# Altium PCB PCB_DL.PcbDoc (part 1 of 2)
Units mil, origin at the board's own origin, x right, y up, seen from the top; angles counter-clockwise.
Board outline 3150 x 3254.21 mil, 2 copper layers (Top Layer, Bottom Layer); 110 components, 96 nets, 420 pads, 120 vias.
Unrouted connection lines stored in the file: 79.
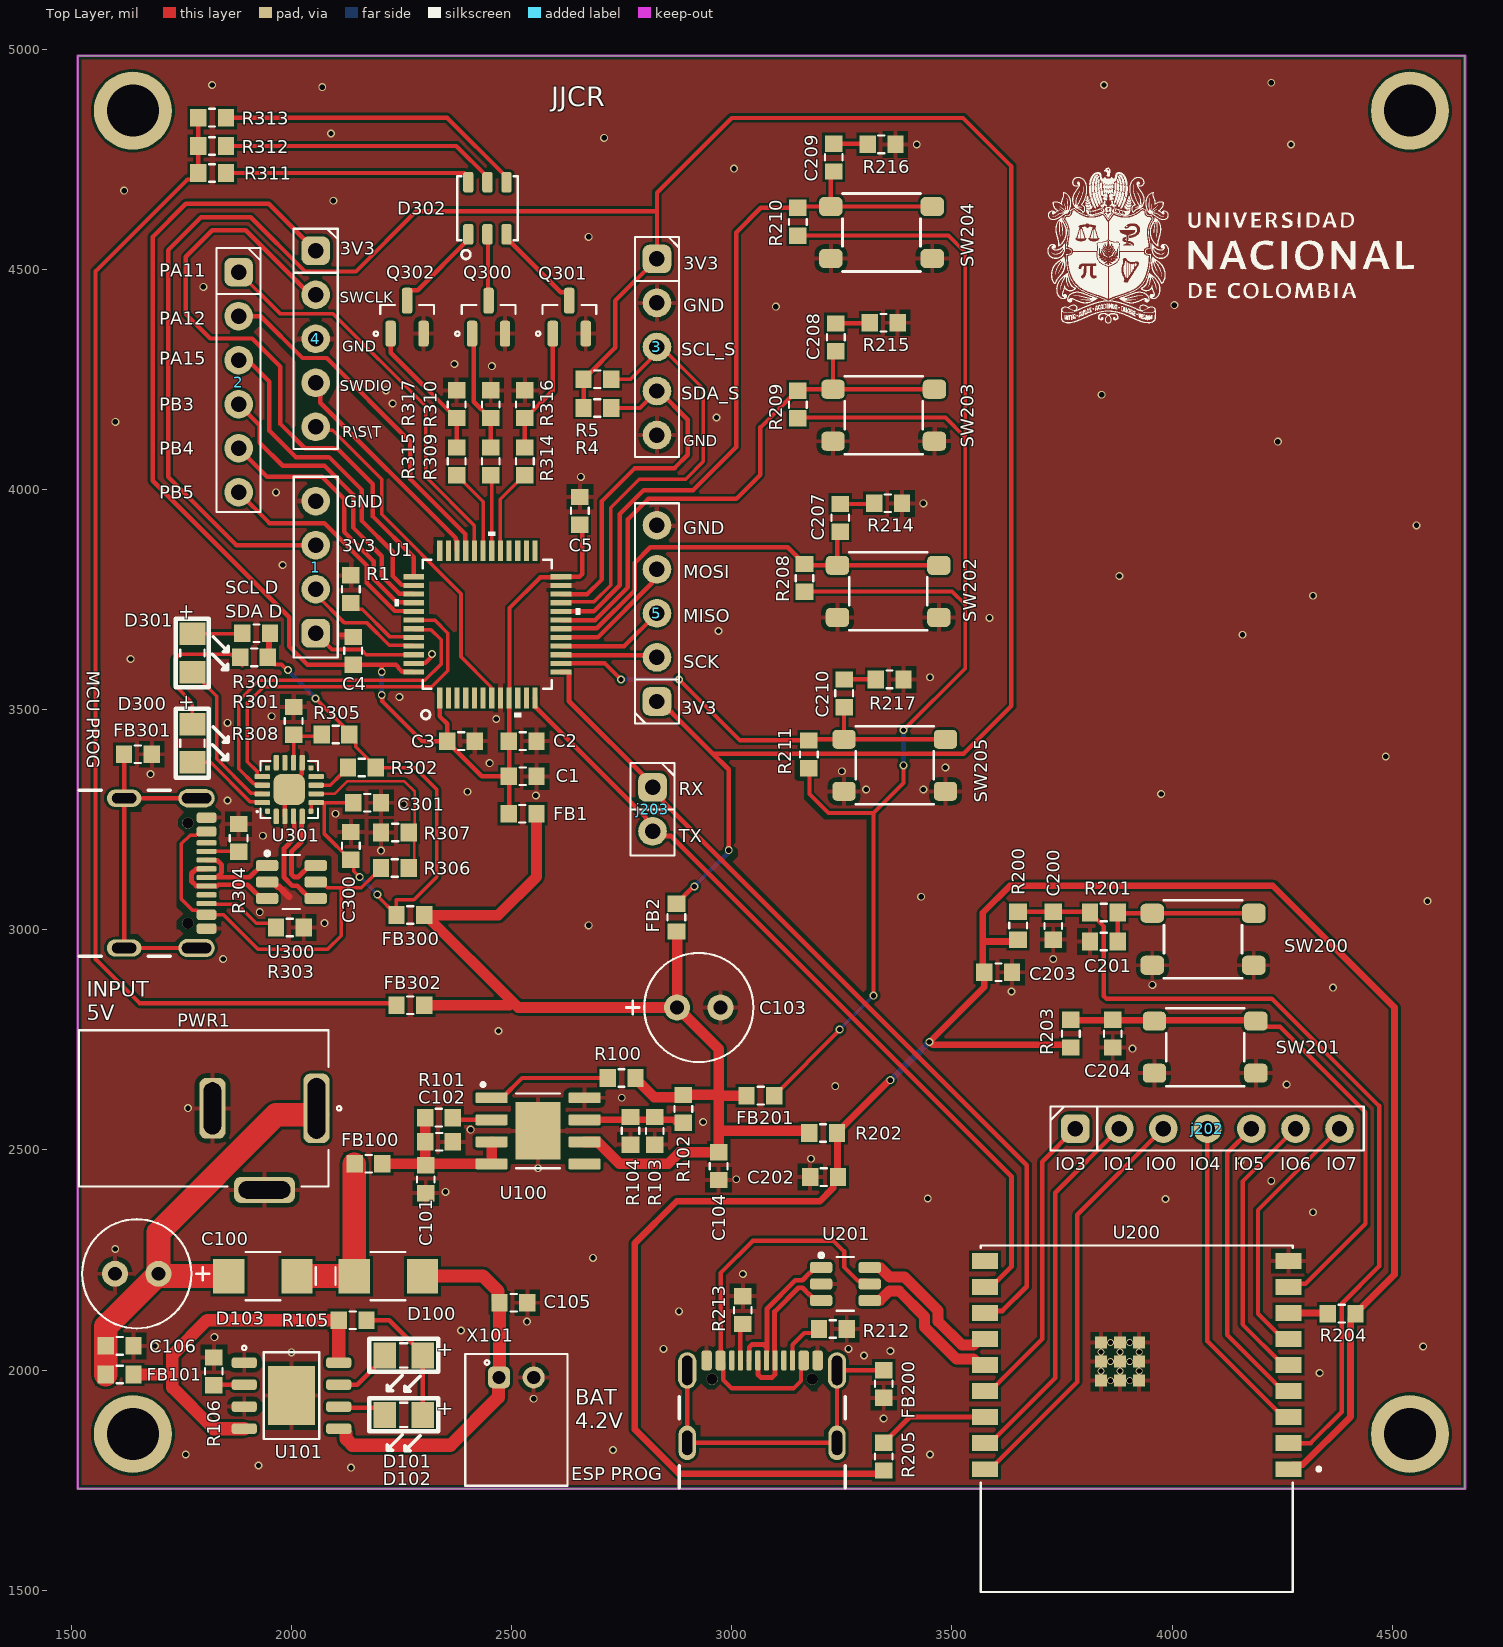
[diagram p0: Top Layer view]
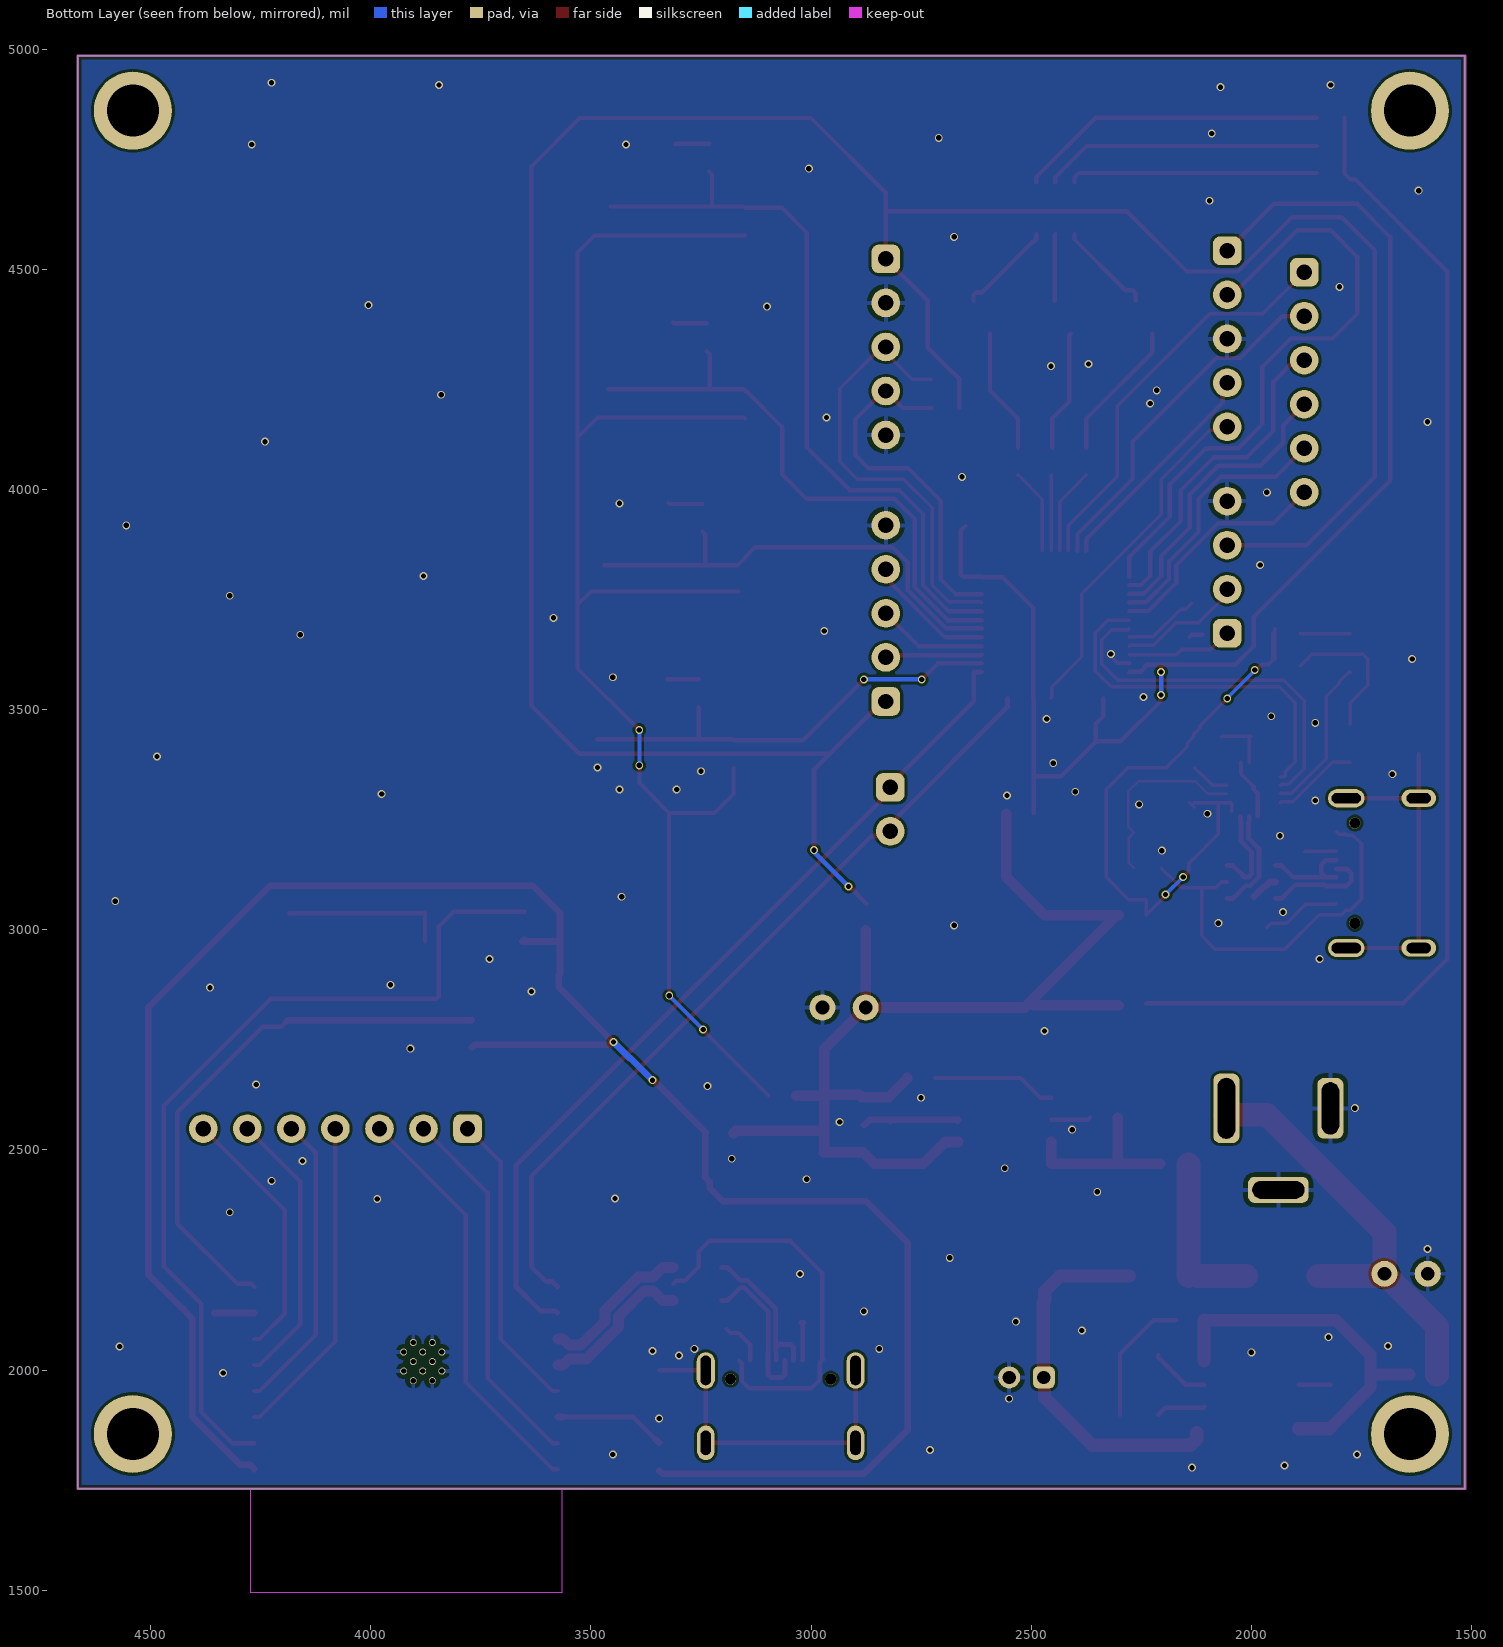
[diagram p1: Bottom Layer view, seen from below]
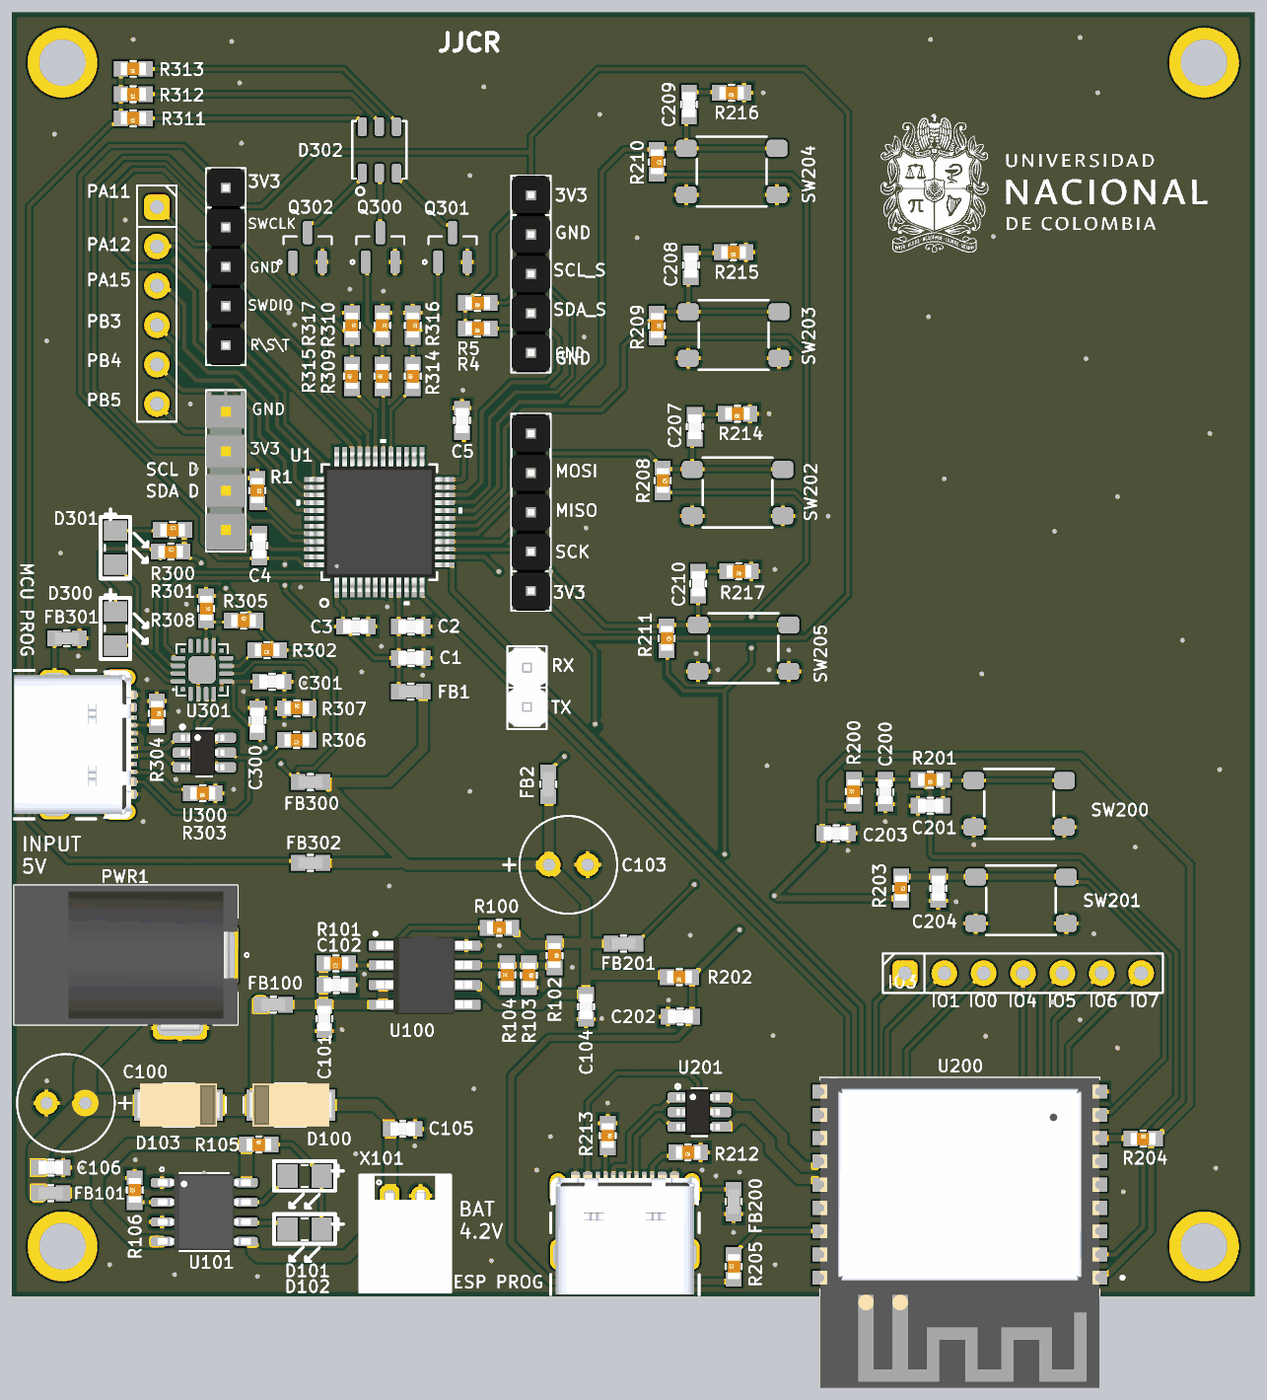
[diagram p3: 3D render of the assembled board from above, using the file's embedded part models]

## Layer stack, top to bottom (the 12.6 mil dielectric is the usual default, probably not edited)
Top Solder: solder mask 0.4, Solder Resist, Dk 3.5
Top Layer: signal copper 1.4
Dielectric 1: dielectric 12.6, FR-4, Dk 4.8
Bottom Layer: signal copper 1.4
Bottom Solder: solder mask 0.4, Solder Resist, Dk 3.5

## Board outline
1515,1730.39 4665,1730.39 4665,4984.61 1515,4984.61

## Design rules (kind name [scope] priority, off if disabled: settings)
Clearance [All] p1: gap=6 ignorepadtopadclearanceinfootprint=FALSE
DiffPairsRouting [InDifferentialPairClass('USB_2.0')] p1: maxlimit=6 minlimit=6 mostfreqgap=6 toplayer_minwidth=11 toplayer_maxwidth=31 toplayer_prefwidth=31 bottomlayer_minwidth=11 bottomlayer_maxwidth=31 bottomlayer_prefwidth=31 maxuncoupledlength=500
HoleSize [All] p1: absolutevalues=TRUE maxlimit=200 minlimit=12 maxpercent=80.000 minpercent=20.000
MatchedLengths [InDifferentialPairClass('USB_2.0')] p1: tolerance=50 checknetsindiffpair=TRUE checkdiffpairvsdiffpair=FALSE checkxsignals=FALSE checkothers=FALSE
MinimumSolderMaskSliver [All] p1: minsoldermaskwidth=4
PolygonConnect PolygonConnect_1 [IsVia] p1: connectstyle=Direct reliefconductorwidth=10 reliefentries=4 polygonreliefangle="90 Angle" airgapwidth=10
PolygonConnect [All] p2: connectstyle=Relief reliefconductorwidth=10 reliefentries=4 polygonreliefangle="90 Angle" airgapwidth=10
RoutingVias [All] p1: holewidth=12 width=18 viastyle="Through Hole" minholewidth=12 minwidth=18 maxholewidth=50 maxwidth=50
SilkToSilkClearance [All] p1: silktosilkclearance=0.1
SilkToSolderMaskClearance [IsPad] p1: minsilkscreentomaskgap=1 clearancetoexposedcopper=TRUE
SolderMaskExpansion [All] p1: expansion=4 istentingtop=FALSE
SupplyNets "Schematic Supply Nets_12" [InNet('3V3_BTN')] p1: voltage=0.000
SupplyNets "Schematic Supply Nets_11" [InNet('3V3_EXT')] p2: voltage=0.000
SupplyNets "Schematic Supply Nets_10" [InNet('3V3_LED')] p3: voltage=0.000
SupplyNets "Schematic Supply Nets_9" [InNet('VBUS2')] p4: voltage=0.000
SupplyNets "Schematic Supply Nets_8" [InNet('VBAT')] p5: voltage=0.000
SupplyNets "Schematic Supply Nets_7" [InNet('3V3')] p6: voltage=0.000
SupplyNets "Schematic Supply Nets_6" [InNet('VLDO')] p7: voltage=0.000
SupplyNets "Schematic Supply Nets_5" [InNet('3V3_CP')] p8: voltage=0.000
SupplyNets "Schematic Supply Nets_4" [InNet('GND')] p9: voltage=0.000
SupplyNets "Schematic Supply Nets_3" [InNet('5V')] p10: voltage=0.000
SupplyNets "Schematic Supply Nets_2" [InNet('3V3_MCU')] p11: voltage=0.000
SupplyNets "Schematic Supply Nets_1" [InNet('3V3_ESP')] p12: voltage=0.000
SupplyNets "Schematic Supply Nets" [InNet('VBUS')] p13: voltage=0.000
Width Width_2 [InNet('5V')] p1: maxlimit=54 minlimit=50 preferedwidth=54
Width Width_6 [InNet('VLDO')] p2: maxlimit=54 minlimit=50 preferedwidth=54
Width Width_4 [InNet('3V3_ESP')] p3: maxlimit=15 minlimit=10 preferedwidth=15
Width [InNet('3V3')] p4: maxlimit=24 minlimit=24 preferedwidth=24
Width Width_7 [InNet('VBAT')] p5: maxlimit=30 minlimit=30 preferedwidth=30
Width Width_3 [InNet('3V3_MCU')] p6: maxlimit=10 minlimit=8 preferedwidth=10
Width Width_5 [InNet('3V3_CP')] p7: maxlimit=10 minlimit=8 preferedwidth=10
Width Width_1 [All] p8: maxlimit=100 minlimit=6 preferedwidth=10
25 further rules are at their usual default settings.

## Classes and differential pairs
component class POWER: C100 C101 C102 C103 C104 C105 C106 D100 D101 D102 D103 FB100 FB101 PWR1 R100 R101 R102 R103 R104 R105 R106 U100 U101 X101
component class MCU: 1 2 3 4 5 C1 C2 C3 C4 C5 FB1 FB2 R1 R4 R5 U1
component class CP2102: C300 C301 D300 D301 D302 FB300 FB301 FB302 "MCU PROG" Q300 Q301 Q302 R300 R301 R302 R303 R304 R305 R306 R307 R308 R309 R310 R311 R312 R313 R314 R315 R316 R317 U300 U301
differential pair class USB_2.0: D2_C D_C DATA DATA_ESP DATA_MCU
component class ESP: C200 C201 C202 C203 C204 C207 C208 C209 C210 "ESP PROG" FB200 FB201 j200 j202 j203 R200 R201 R202 R203 R204 R205 R208 R209 R210 R211 R212 R213 R214 R215 R216 R217 SW200 SW201 SW202 SW203 SW204 SW205 U200 U201
differential pair D2_C: +D2_C_P -D2_C_N
differential pair DATA_MCU: +DATA_MCU_P -DATA_MCU_N
differential pair DATA_ESP: +DATA_ESP_P -DATA_ESP_N
differential pair D_C: +D_C_P -D_C_N

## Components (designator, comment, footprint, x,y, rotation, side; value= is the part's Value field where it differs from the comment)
1 "4x1" H_4x1_TH_2.54mm 2055.07,3823.5 r90 top
2 "6x1" H_6x1_TH_100mil 1880.07,4243.5 r270 top
3 "5x1" H_5x1_TH_100mil 2830.07,4323.5 r270 top
4 "5x1" H_5x1_TH_100mil 2055,4342 r270 top
5 "5x1" H_5x1_TH_100mil 2830.07,3718.5 r90 top
C1 "10uF 10V" 0603_cap 2525.07,3348.5 r0 top value=10uF
C2 "0.1uF 50V" 0603_cap 2525.07,3428.5 r0 top value=0.1uF
C3 "0.1uF 50V" 0603_cap 2385.07,3428.5 r0 top value=0.1uF
C4 "0.1uF 50V" 0603_cap 2140.07,3633.5 r90 top value=0.1uF
C5 "0.1uF 50V" 0603_cap 2655.07,3951.5 r90 top value=0.1uF
C100 "100uF 35V" CAP_TH_2.5MM_6.3*12MM 1648.75,2218.82 r180 top value=100uF
C101 "10uF 10V" 0603_cap 2305.07,2433.5 r270 top value=10uF
C102 "1uF 50V" 0603_cap 2335.07,2518.5 r0 top value=1uF
C103 "100uF 35V" CAP_TH_2.5MM_6.3*12MM 2925.07,2823.5 r0 top value=100uF
C104 "10uF 10V" 0603_cap 2970.07,2463.5 r270 top value=10uF
C105 "10uF 10V" 0603_cap 2504.18,2153.02 r0 top value=10uF
C106 "10uF 10V" 0603_cap 1610,2055 r0 top value=10uF
C200 "0.1uF 50V" 0603_cap 3730.07,3009.21 r270 top value=0.1uF
C201 "0.1uF 50V" 0603_cap 3845.07,2973.5 r180 top value=0.1uF
C202 "10uF 10V" 0603_cap 3209.57,2438.5 r180 top value=10uF
C203 "0.1uF 50V" 0603_cap 3605.07,2903.5 r0 top value=0.1uF
C204 "0.1uF 50V" 0603_cap 3865.07,2764.21 r270 top value=0.1uF
C207 "0.1uF 50V" 0603_cap 3246.49,3935.5 r90 top value=0.1uF
C208 "0.1uF 50V" 0603_cap 3236.49,4345.5 r90 top value=0.1uF
C209 "0.1uF 50V" 0603_cap 3231.49,4753.5 r90 top value=0.1uF
C210 "0.1uF 50V" 0603_cap 3255.07,3537 r90 top value=0.1uF
C300 "10uF 10V" 0603_cap 2135.07,3190.5 r90 top value=10uF
C301 "0.1uF 50V" 0603_cap 2172.07,3288.5 r0 top value=0.1uF
D100 "30V 3A" SMA 2220.07,2213.5 r0 top
D101 "2.9V" 0805_LED 2255.07,1898.5 r180 top
D102 "2V" 0805_LED 2255.07,2033.5 r180 top
D103 "30V 3A" SMA 1935.07,2213.5 r180 top
D300 "2V" 0805_LED 1775.07,3423.5 r270 top
D301 "2.9V" 0805_LED 1775.07,3628.5 r270 top
D302 "RGB" RGB_NS_3.5X3.7 2445.07,4638.5 r90 top
"ESP PROG" "USB C" CON_USB_C_16P_RA#1 3068.93,1928.38 r0 top
FB1 "60OHM 2A" 0603_fb 2525.07,3263.5 r180 top value="60 OHM"
FB2 "60OHM 2A" 0603_fb 2874.36,3027.75 r90 top value="60 OHM"
FB100 "60OHM 2A" 0603_fb 2175.07,2468.5 r0 top value="60 OHM"
FB101 "60OHM 2A" 0603_fb 1610,1990.17 r0 top value="60 OHM"
FB200 "60OHM 2A" 0603_fb 3345.07,1968.5 r90 top value="60 OHM"
FB201 "60OHM 2A" 0603_fb 3065.07,2623.5 r0 top value="60 OHM"
FB300 "60OHM 2A" 0603_fb 2270.07,3033.5 r180 top value="60 OHM"
FB301 "60OHM 2A" 0603_fb 1651.52,3398.66 r180 top value="60 OHM"
FB302 "60OHM 2A" 0603_fb 2270.07,2828.5 r180 top value="60 OHM"
j202 "7x1" H_7x1_TH_100mil 4080.07,2548.5 r0 top
j203 "2x1" H_2x1_TH_100mil 2820.07,3273.5 r270 top
"MCU PROG" "USB C" CON_USB_C_16P_RA#2 1713.62,3128.66 r270 top
PWR1 "PWR JACK 2.1mm" CON_POWER_BARREL_2.1MM_3CONN 1938.83,2594.54 r270 top
Q300 "N CH" SOT_23_3 2447.67,4391.1 r90 top
Q301 "N CH" SOT_23_3 2631.05,4391.1 r90 top
Q302 "N CH" SOT_23_3 2262.67,4391.1 r90 top
R1 "10k 1/10W" 0603_res 2135.07,3773.5 r270 top value=10k
R4 "4k7 1/10W" 0603_res 2695,4185 r180 top value=4k7
R5 "4k7 1/10W" 0603_res 2695,4250 r180 top value=4k7
R100 "73k2 1/10W" 0603_res 2750.07,2663.5 r180 top value=73k2
R101 "33k2 1/10W" 0603_res 2335.07,2573.5 r180 top value=33k2
R102 "73k2 1/10W" 0603_res 2890.07,2593.5 r270 top value=73k2
R103 "33k2 1/10W" 0603_res 2825.07,2543.5 r270 top value=33k2
R104 "73k2 1/10W" 0603_res 2770.07,2543.5 r90 top value=73k2
R105 "1k 1/10W" 0603_res 2138.85,2113.5 r0 top value=1k
R106 "1k 1/10W" 0603_res 1823.79,1997.3 r90 top value=1k
R200 "10k 1/10W" 0603_res 3650.07,3009.21 r90 top value=10k
R201 "0R 1/10W" 0603_res 3845.07,3039.21 r180 top value=0R
R202 "0R 1/10W" 0603_res 3207.57,2538.5 r180 top value=0R
R203 "10k 1/10W" 0603_res 3770.07,2764.21 r270 top value=10k
R204 "10k 1/10W" 0603_res 4385.07,2128.5 r0 top value=10k
R205 "10k 1/10W" 0603_res 3345.07,1803.5 r90 top value=10k
R208 "4k7 1/10W" 0603_res 3165.07,3799.21 r270 top value=4k7
R209 "4k7 1/10W" 0603_res 3150.07,4192.9 r270 top value=4k7
R210 "4k7 1/10W" 0603_res 3150.07,4607.9 r270 top value=4k7
R211 "4k7 1/10W" 0603_res 3175.07,3398.5 r270 top value=4k7
R212 "4k7 1/10W" 0603_res 3229.57,2093.5 r180 top value=4k7
R213 "4k7 1/10W" 0603_res 3025.07,2136.5 r270 top value=4k7
R214 "100R 1/10W" 0603_res 3355.07,3968.5 r180 top value=100R
R215 "100R 1/10W" 0603_res 3345.07,4378.5 r180 top value=100R
R216 "100R 1/10W" 0603_res 3340.07,4783.5 r180 top value=100R
R217 "100R 1/10W" 0603_res 3358.57,3568.5 r180 top value=100R
R300 "150R 1/10W" 0603_res 1915.07,3618.5 r0 top value=150R
R301 "84R5 1/10W" 0603_res 1920.07,3673.5 r0 top value=84R5
R302 "1k 1/10W" 0603_res 2160.07,3368.5 r180 top value=1k
R303 "4k7 1/10W" 0603_res 1996.58,3005.25 r180 top value=4k7
R304 "4k7 1/10W" 0603_res 1880.07,3208.5 r270 top value=4k7
R305 "10k 1/10W" 0603_res 2100.07,3443.5 r0 top value=10k
R306 "33k2 1/10W" 0603_res 2235.07,3140.25 r180 top value=33k2
R307 "54k9 1/10W" 0603_res 2235.07,3220.95 r0 top value=54k9
R308 "10k 1/10W" 0603_res 2005.07,3474.5 r270 top value=10k
R309 "10k 1/10W" 0603_res 2452.57,4063.5 r90 top value=10k
R310 "10k 1/10W" 0603_res 2452.57,4193.5 r270 top value=10k
R311 "330R 1/10W" 0603_res 1820.16,4718.51 r180 top value=330R
R312 "330R 1/10W" 0603_res 1820.16,4779.86 r180 top value=330R
R313 "330R 1/10W" 0603_res 1820.16,4844.3 r180 top value=330R
R314 "10k 1/10W" 0603_res 2530.07,4063.5 r90 top value=10k
R315 "10k 1/10W" 0603_res 2375.07,4063.5 r90 top value=10k
R316 "10k 1/10W" 0603_res 2530.07,4193.5 r270 top value=10k
R317 "10k 1/10W" 0603_res 2375.07,4193.5 r270 top value=10k
SW200 "Sw" Sw_PUSH_4.5x4.5x5mm 4070.07,2978.5 r180 top
SW201 "Sw" Sw_PUSH_4.5x4.5x5mm 4075.07,2733.5 r180 top
SW202 "Sw" Sw_PUSH_4.5x4.5x5mm 3355.07,3768.5 r180 top
SW203 "Sw" Sw_PUSH_4.5x4.5x5mm 3345.07,4168.5 r180 top
SW204 "Sw" Sw_PUSH_4.5x4.5x5mm 3340.07,4583.5 r180 top
SW205 "Sw" Sw_PUSH_4.5x4.5x5mm 3370.07,3373.5 r180 top
U1 "STM32F030C8T6TR" LQFP48_7x7mm 2445.07,3693.5 r90 top
U100 "MG6145S8-AJ" LDO_3A_ADJ 2560.07,2543.5 r0 top
U101 "4.2V 1A" SOIC_8_3.9mm_EP 2000.08,1942.01 r0 top
U200 "ESP32-C3-WROOM-02-N4" ESP32-C3-WROOM-02-N4 3919.56,2011.61 r180 top
U201 "USBLC6-2SC6" SOT_23_6 3258.08,2195.76 r0 top
U300 "USBLC6-2SC6" SOT_23_6 2000.07,3108.5 r0 top
U301 "CP2102N-A02-GQFN20R" WFQFN_20_EP_3X3MM 1995.07,3318.5 r90 top
X101 "Connector 2pos" CON_2x1_TH_2MM 2510.7,1983.5 r0 top

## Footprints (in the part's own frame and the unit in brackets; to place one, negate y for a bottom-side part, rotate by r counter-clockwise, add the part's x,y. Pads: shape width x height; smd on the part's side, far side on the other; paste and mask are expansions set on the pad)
0603_cap [mil]
  rect 37x40 smd: 1(-31.5,0) 2(31.5,0)
  silkscreen extent -6,-20 8,20, body extent -31,-17 31,17, height 34
0603_fb [mil]
  rect 37x40 smd: 1(-31.5,0) 2(31.5,0)
  silkscreen extent -7,-20 8,20, body extent -32,-16 31,16, height 32
0603_res [mil] "1608 Metric / 20190225 / C-A.Serna.A"
  rect 37x40 smd: 1(-31.5,0) 2(31.5,0)
  silkscreen extent -7,-20 8,20, body extent -31,-16 32,16, height 12
0805_LED [mm]
  rect 1.3x1.5 smd: 1(-1.1,0) 2(1.1,0)
  silkscreen extent -1.98,-0.97 1.98,2.07, body extent -1,-0.62 1,0.63, height 1.1
CAP_TH_2.5MM_6.3*12MM [mm]
  round 1.5 hole 0.8: 1(-1.25,0) 2(1.25,0)
  silkscreen extent -4.19,-3.15 3.15,3.15, body extent -3.15,-3.15 3.15,3.15, height 12
CON_2x1_TH_2MM [mil] "/20190307/N-A.Potosi"
  rrect50% 50x50 hole 30: 1(-39.37,0)
  round 50 hole 30: 2(39.37,0)
  silkscreen extent -116,-246 116,53, body extent -117,-247 116,52, height 189
CON_POWER_BARREL_2.1MM_3CONN [mm]
  rrect50% 4x1.5 hole 1.016 slot 3.5 at 0 deg: 1(0,3)
  rrect50% 3.5x1.5 hole 1.016 slot 3 at 0 deg: 2(0,-3)
  rrect50% 1.5x3.5 hole 1.016 slot 3 at 90 deg: 3(4.7,0)
  silkscreen extent -4.5,-10.7 4.5,4.43, body extent -4.5,-10.7 4.9,3.7, height 11
CON_USB_C_16P_RA#1 [mm]
  oval 1x2 hole 0.6 slot 1.4 at 90 deg: 0(-4.32,-2.377) 0(4.32,-2.377)
  oval 1.05x2.1 hole 0.6 slot 1.7 at 90 deg: 0(-4.32,1.803) 0(4.32,1.803)
  rrect50% 0.6x1.15 smd mask+0.046: A1/B12(-3.2,2.378) A4/B9(-2.4,2.378) B1/A12(3.2,2.378) B4/A9(2.4,2.378)
  rrect50% 0.3x1.15 smd mask+0.046: A5(-1.25,2.378) A6(-0.25,2.378) A7(0.25,2.378) A8(1.25,2.378) B5(1.75,2.378) B6(0.75,2.378) B7(-0.75,2.378) B8(-1.75,2.378)
  round 0.65 hole 0.65 unplated mask+0.046: ""(-2.89,1.303) ""(2.89,1.303)
  silkscreen extent -4.79,-4.98 4.79,0.27, body extent -4.79,-4.98 4.79,2.73, height 3.31
CON_USB_C_16P_RA#2 [mm]
  oval 1.05x2.1 hole 0.6 slot 1.7 at 90 deg: 0(-4.32,1.803) 0(4.32,1.803)
  oval 1x2 hole 0.6 slot 1.4 at 90 deg: 0(-4.32,-2.377) 0(4.32,-2.377)
  rrect50% 0.6x1.15 smd mask+0.046: A1/B12(-3.2,2.378) A4/B9(-2.4,2.378) B1/A12(3.2,2.378) B4/A9(2.4,2.378)
  rrect50% 0.3x1.15 smd mask+0.046: A5(-1.25,2.378) A6(-0.25,2.378) A7(0.25,2.378) A8(1.25,2.378) B5(1.75,2.378) B6(0.75,2.378) B7(-0.75,2.378) B8(-1.75,2.378)
  round 0.65 hole 0.65 unplated mask+0.046: ""(-2.89,1.303)
  round 0.65 hole 0.65 unplated mask+0.047: ""(2.89,1.303)
  silkscreen extent -4.79,-4.98 4.79,0.27, body extent -4.79,-4.98 4.79,2.73, height 3.31
ESP32-C3-WROOM-02-N4 [mm]
  rect 1.5x0.9 smd: 1(-8.75,6) 2(-8.75,4.5) 3(-8.75,3) 4(-8.75,1.5) 5(-8.75,0) 6(-8.75,-1.5) 7(-8.75,-3) 8(-8.75,-4.5) 9(-8.75,-6) 10(8.75,-6) 11(8.75,-4.5) 12(8.75,-3) 13(8.75,-1.5) 14(8.75,0) 15(8.75,1.5) 16(8.75,3) 17(8.75,4.5) 18(8.75,6)
  rect 0.7x0.7 smd mask+0.102: 19(-0.14,0.9) 19(-0.14,-0.2) 19(-0.14,-1.3) 19(0.96,0.9) 19(0.96,-0.2) 19(0.96,-1.3) 19(2.06,-1.3) 19(2.06,-0.2) 19(2.06,0.9)
  round 0.4 hole 0.305 mask+0: 19(-0.14,0.35) 19(-0.14,-0.75) 19(0.41,0.9) 19(0.41,-0.2) 19(0.41,-1.3) 19(0.96,0.35) 19(0.96,-0.75) 19(1.51,0.9) 19(1.51,-0.2) 19(1.51,-1.3) 19(2.06,-0.75) 19(2.06,0.35)
  Keep-Out Layer region: 9,7.1 -9,7.1 -9,13.1 9,13.1
  Keep-Out Layer region: 9,7.1 -9,7.1 -9,13.1 9,13.1
  silkscreen extent -10.6,-6.9 9,13.1, body extent -9,-6.9 9,13.1, height 3.35
H_2x1_TH_100mil [mil]
  rrect50% 65x65 hole 35: 1(-50,0)
  round 65 hole 35: 2(50,0)
  silkscreen extent -105,-50 105,50, body extent -101,-49 99,49, height 339
H_4x1_TH_2.54mm [mil]
  rrect50% 65x65 hole 35: 1(-150,0)
  round 65 hole 35: 2(-50,0) 3(50,0) 4(150,0)
  silkscreen extent -205,-50 205,50, body extent -200,-50 205,50, height 420
H_5x1_TH_100mil [mil]
  rrect50% 65x65 hole 35: 1(-200,0)
  round 65 hole 35: 2(-100,0) 3(0,0) 4(100,0) 5(200,0)
  silkscreen extent -250,-50 250,50, body extent -250,-49 250,49, height 335
H_6x1_TH_100mil [mil]
  rrect50% 65x65 hole 35: 1(-250,0)
  round 65 hole 35: 2(-150,0) 3(-50,0) 4(50,0) 5(150,0) 6(250,0)
  silkscreen extent -305,-50 295,50
H_7x1_TH_100mil [mil]
  rrect50% 65x65 hole 35: 1(-300,0)
  round 65 hole 35: 2(-200,0) 3(-100,0) 4(0,0) 5(100,0) 6(200,0) 7(300,0)
  silkscreen extent -356,-50 355,50
LDO_3A_ADJ [mm]
  rrect25% 1.865x0.63 smd mask+0.102: 1(-2.682,1.905) 2(-2.682,0.635) 3(-2.682,-0.635) 4(-2.682,-1.905) 5(2.682,-1.905) 6(2.682,-0.635) 7(2.682,0.635) 8(2.682,1.905)
  rect 2.6x3.3 smd paste-3 mask+0.102: 9(0,0)
  silkscreen extent -3.27,-2.16 1.27,2.77, body extent -3.13,-2.52 3.07,2.48, height 1.74
LQFP48_7x7mm [mil]
  rect 47x12 smd paste+0 mask+1.8: 1(-167.32,108.27) 2(-167.32,88.58) 3(-167.32,68.9) 4(-167.32,49.21) 5(-167.32,29.53) 6(-167.32,9.84) 7(-167.32,-9.84) 8(-167.32,-29.53) 9(-167.32,-49.21) 10(-167.32,-68.9) 11(-167.32,-88.58) 12(-167.32,-108.27) 25(167.32,-108.27) 26(167.32,-88.58) 27(167.32,-68.9) 28(167.32,-49.21) 29(167.32,-29.53) 30(167.32,-9.84) 31(167.32,9.84) 32(167.32,29.53) 33(167.32,49.21) 34(167.32,68.9) 35(167.32,88.58) 36(167.32,108.27)
  rect 12x47 smd paste+0 mask+1.8: 13(-108.27,-167.32) 14(-88.58,-167.32) 15(-68.9,-167.32) 16(-49.21,-167.32) 17(-29.53,-167.32) 18(-9.84,-167.32) 19(9.84,-167.32) 20(29.53,-167.32) 21(49.21,-167.32) 22(68.9,-167.32) 23(88.58,-167.32) 24(108.27,-167.32) 37(108.27,167.32) 38(88.58,167.32) 39(68.9,167.32) 40(49.21,167.32) 41(29.53,167.32) 42(9.84,167.32) 43(-9.84,167.32) 44(-29.53,167.32) 45(-49.21,167.32) 46(-68.9,167.32) 47(-88.58,167.32) 48(-108.27,167.32)
  silkscreen extent -215,-211 211,211, body extent -177,-177 177,177, height 63
RGB_NS_3.5X3.7 [mm]
  rrect50% 1.2x0.6 smd: 1(-1.5,1.1) 2(-1.5,0) 3(-1.5,-1.1) 4(1.5,-1.1) 5(1.5,0) 6(1.5,1.1)
  silkscreen extent -2.92,-1.75 1.85,1.75, body extent -1.85,-1.74 1.85,1.75, height 1
SMA [mm]
  rect 1.8x2 smd: 1(-1.965,0) 2(1.965,0)
  silkscreen extent -3.05,-1.4 0.98,1.4, body extent -2.64,-1.4 2.64,1.4, height 2.34
SOIC_8_3.9mm_EP [mm]
  rrect50% 1.45x0.6 smd: 1(-2.725,1.905) 2(-2.725,0.635) 3(-2.725,-0.635) 4(-2.725,-1.905) 5(2.725,-1.905) 6(2.725,-0.635) 7(2.725,0.635) 8(2.725,1.905)
  rect 2.71x3.4 smd: 9(0,0)
  silkscreen extent -2.85,-2.5 1.6,2.88, body extent -3,-2.45 3,2.45, height 1.7
SOT_23_3 [mm]
  rrect50% 1.5x0.6 smd: 1(-0.95,0.95) 2(-0.95,-0.95) 3(0.95,0)
  silkscreen extent -1.07,-1.55 0.7,1.92, body extent -0.7,-1.52 0.7,1.53, height 1.12
SOT_23_6 [mm]
  rrect50% 1.3x0.65 smd mask+0.094: 1(-1.4,0.95) 2(-1.4,0) 3(-1.4,-0.95) 4(1.4,-0.95) 5(1.4,0) 6(1.4,0.95)
  silkscreen extent -1.52,-1.55 0.5,1.78, body extent -1.5,-1.45 1.3,1.45, height 1.45
Sw_PUSH_4.5x4.5x5mm [mm]
  rrect50% 1.35x1.1 smd: 1(-2.925,1.5) 1(2.925,1.5) 2(-2.925,-1.5) 2(2.925,-1.5)
  silkscreen extent -2.25,-2.25 2.25,2.25, body extent -2.25,-2.25 2.25,2.25, height 5
WFQFN_20_EP_3X3MM [mm]
  rrect50% 0.3x0.3 smd mask+0.046: 1(-1.25,1.25) 6(-1.25,-1.25) 11(1.25,-1.25)
  rrect50% 0.9x0.3 smd mask+0.048: 2(-1.55,0.75) 3(-1.55,0.25) 4(-1.55,-0.25) 5(-1.55,-0.75) 12(1.55,-0.75) 13(1.55,-0.25) 14(1.55,0.25) 15(1.55,0.75)
  rrect50% 0.3x0.9 smd mask+0.048: 7(-0.75,-1.55) 8(-0.25,-1.55) 9(0.25,-1.55) 10(0.75,-1.55) 17(0.75,1.55) 18(0.25,1.55) 19(-0.25,1.55) 20(-0.75,1.55)
  rect 0.3x0.3 smd mask+0.046: 16(1.25,1.25)
  rrect50% 1.8x1.8 smd mask+0.048: 21(0,0)
  silkscreen extent -1.65,-1.65 1.65,1.9, body extent -1.5,-1.5 1.5,1.5, height 0.8

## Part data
1: library part H_Male_4x1_TH_100mil, "H_Male_4x1_TH_100mil"
2: library part H_Male_6x1_TH_100mil, "H_Male_6x1_TH_100mil"
3 4 5: library part H_Male_5x1_TH_100mil, "H_Male_5x1_TH_100mil"
C1 C101 C104 C105 C106 C202 C300: library part Cap_10uF_0603_10V, "10V 10uF X5R ±10% 0603 Multilayer Ceramic Capacitors MLCC - SMD/SMT ROHS", Manufacturer=CCTC, Manufacturer Part Number=TCC0603X5R106K100CT, Supplier Part Number 1=C380314
C2 C3 C4 C5 C200 C201 C203 C204 C207 C208 C209 C210 C301: library part Cap_0.1uF_0603_50V, "50V 100nF Y5V -20%~+80% 0603 Multilayer Ceramic Capacitors MLCC - SMD/SMT ROHS", Manufacturer="Walsin Tech Corp", Manufacturer Part Number=0603F104Z500CT, Supplier Part Number 1=C83060
C100 C103: library part Cap_100uF_ALU_TH_35V, "100uF 35V ±20% Plugin,D6.3xL12mm Aluminum Electrolytic Capacitors - Leaded ROHS", Manufacturer=HRK, Manufacturer Part Number="35V100uF CD110", Supplier Part Number 1=C2960381
C102: library part Cap_1uF_0603_50V, "50V 1uF X5R ±10% 0603 Multilayer Ceramic Capacitors MLCC - SMD/SMT ROHS", Manufacturer="Samsung Electro-Mechanics", Manufacturer Part Number=CL10A105KB8NNNC, Supplier Part Number 1=C15849
D100 D103: library part D_Schottky_40V_3A_SMA, "40V Independent 3A 550mV@3A SMA Schottky Diodes ROHS", Manufacturer=TDSEMIC, Manufacturer Part Number=SS34-TD, Supplier Part Number 1=C46550832
D101 D301: library part LED_0805_Green, "LED GREEN CLEAR 0805 SMD", Manufacturer=XINGLIGHT, Manufacturer Part Number=XL-2012UGC, Supplier Part Number 1=C965815
D102 D300: library part LED_0805_RED, "LED RED CLEAR 0805 SMD", Manufacturer=XINGLIGHT, Manufacturer Part Number=XL-2012SURC, Supplier Part Number 1=C965812
D302: library part LED_RGB_3535_SMD, "-30℃~+85℃ RGB 110° 3535(mm) Light Emitting Diodes (LED) ROHS", Manufacturer="Foshan NationStar Optoelectronics", Manufacturer Part Number=RS-3535MWAM, Supplier Part Number 1=C842778
"ESP PROG" "MCU PROG": library part CON_USB_TYPEC_16P, "3A USB 3.1 1 Surface Mount 16P Female -40℃~+85℃ Type-C SMD USB Connectors ROHS", Manufacturer="SHOU HAN", Manufacturer Part Number=TYPE-C-3.1-16PIN, Supplier Part Number 1=C7507405
FB1 FB2 FB100 FB101 FB200 FB201 FB300 FB301 FB302: library part FB_60_0603_2A, "2A 1 100mΩ 60Ω@100MHz ±25% 0603 Ferrite Beads ROHS", Manufacturer=TAI-TECH, Manufacturer Part Number=HCB1608KF-600T20, Supplier Part Number 1=C369516
j202: library part H_Male_7x1_TH_100mil, "H_Male_7x1_TH_100mil"
j203: library part H_Male_2x1_TH_100mil, "H_Male_2x1_TH_100mil"
PWR1: library part Con_Power_Jack_2.1mm_3pins, "CONN PWR JACK 2X5.5MM SOLDER", Manufacturer=HCTL, Manufacturer Part Number=HC-DC-005-2.0T, Supplier Part Number 1=C3010533
Q300 Q301 Q302: library part Q_NFET_20V_3.2A_SOT23, "MOSFET N-CH 20V SOT23", Manufacturer=Doeshare, Manufacturer Part Number=DN2302S, Supplier Part Number 1=C2931750
R1 R200 R203 R204 R205 R305 R308 R309 R310 R314 R315 R316 R317: library part Res_10k_0603_1/10W, "RES SMD 10k OHM 5% 1/10W 0603", Manufacturer=FOJAN, Manufacturer Part Number=FRC0603J103TS, Supplier Part Number 1=C2930027
R4 R5 R208 R209 R210 R211 R212 R213 R303 R304: library part Res_4k7_0603_1/10W, "100mW Thick Film Resistor 75V ±1% 4.7kΩ 0603 Chip Resistor - Surface Mount ROHS", Manufacturer=VO, Manufacturer Part Number=SCR0603F4K7, Supplier Part Number 1=C3016318
R100 R102 R104: library part Res_73k2_0603_1/10W, "100mW Thick Film Resistor 75V ±100ppm/℃ ±1% 73.2kΩ 0603 Chip Resistor - Surface Mount ROHS", Manufacturer=YAGEO, Manufacturer Part Number=RC0603FR-0773K2L, Supplier Part Number 1=C163420
R101 R103 R306: library part Res_33k2_0603_1/10W, "100mW Thick Film Resistor 75V ±100ppm/℃ ±1% 33.2kΩ 0603 Chip Resistor - Surface Mount ROHS", Manufacturer=YAGEO, Manufacturer Part Number=RC0603FR-0733K2L, Supplier Part Number 1=C185338
R105 R106 R302: library part Res_1k_0603_1/10W, "RES SMD 1k OHM 5% 1/10W 0603", Manufacturer=FOJAN, Manufacturer Part Number="FRC0603J102 TS", Supplier Part Number 1=C2907113
R201 R202: library part Res_0R_0603_1/10W, "RES SMD 0R OHM 5% 1/10W 0603", Manufacturer=FOJAN, Manufacturer Part Number="FRC0603P000 TS", Supplier Part Number 1=C2907080
R214 R215 R216 R217: library part Res_100R_0603_1/10W, "RES SMD 100R OHM 5% 1/10W 0603", Manufacturer=FOJAN, Manufacturer Part Number="FRC0603J101 TS", Supplier Part Number 1=C2907089
R300: library part Res_150R_0603_1/10W, "100mW Thick Film Resistor 75V ±100ppm/℃ ±1% 150Ω 0603 Chip Resistor - Surface Mount ROHS", Manufacturer=RALEC, Manufacturer Part Number=RTT031500FTP, Supplier Part Number 1=C103302
R301: library part Res_84R5_0603_1/10W, "100mW Thick Film Resistor 50V ±100ppm/℃ ±1% 84.5Ω 0603 Chip Resistor - Surface Mount ROHS", Manufacturer="LIZ Elec", Manufacturer Part Number=CR0603FA84R5G, Supplier Part Number 1=C101216
R307: library part Res_54k9_0603_1/10W, "100mW Thick Film Resistor 75V ±100ppm/℃ ±1% 54.9kΩ 0603 Chip Resistor - Surface Mount ROHS", Manufacturer=YAGEO, Manufacturer Part Number=RC0603FR-0754K9L, Supplier Part Number 1=C185321
R311 R312 R313: library part Res_330R_0603_1/10W, "RES SMD 330R OHM 5% 1/10W 0603", Manufacturer=FOJAN, Manufacturer Part Number="FRC0603J331 TS", Supplier Part Number 1=C2907152
SW200 SW201 SW202 SW203 SW204 SW205: library part Sw_PUSH_4.5x4.5x5.0xmm, "SWITCH TACTILE SPST-NO 0.05A 12V", Manufacturer=BZCN, Manufacturer Part Number=TSC015A05026A, Supplier Part Number 1=C2888509
U1: library part IC_STM32F030C8T6TR_LQFP48_7x7MM, "IC MCU 32BIT 64KB FLASH 48LQFP", Manufacturer=STMicroelectronics, Supplier Part Number 1=C23922
U100: library part LDO_3A_ADJ, "3A Adjustable 800mV~3.3V Positive 5.5V ESOP-8 Voltage Regulators - Linear, Low Drop Out (LDO) Regulators ROHS", Manufacturer=Megain, Supplier Part Number 1=C22396257
U101: library part IC_BAT_CHG_4.2V_1A, "-300mV~8V Lithium-ion/Polymer 1 1A ESOP-8 Battery Management ROHS", Manufacturer=YONGYUTAI, Manufacturer Part Number=TP4056, Supplier Part Number 1=C20199357
U200: library part MCU_ESP32-C3-WROOM-02-N4, "RF TXRX MOD BT WIFI PCB TH SMD", Manufacturer="Espressif Systems", Supplier Part Number 1=C2934560
U201 U300: library part TVS_5.25V_2CH_SOT_23_6, "TVS DIODE 5.25V 17V SOT23-6", Manufacturer=STMicroelectronics, Supplier Part Number 1=C7519
U301: library part IC_SGL_USB2UART-BRIDGE_20QFN, "IC USB TO UART BRIDGE QFN20", Manufacturer="Silicon Labs", Supplier Part Number 1=C969913
X101: library part Con_2x1_TH_JST_2MM, "2POS 2MM", Manufacturer=JST, Manufacturer Part Number=S2B-PH-K-S(LF)(SN), Supplier Part Number 1=C173752

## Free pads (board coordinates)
  round 177.17 hole 118.11: ""(1640,1855) ""(1640,4860) ""(4540,1855) ""(4540,4860)

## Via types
v1: diameter 18, hole 12, Top Layer to Bottom Layer, tented both sides, 120 vias

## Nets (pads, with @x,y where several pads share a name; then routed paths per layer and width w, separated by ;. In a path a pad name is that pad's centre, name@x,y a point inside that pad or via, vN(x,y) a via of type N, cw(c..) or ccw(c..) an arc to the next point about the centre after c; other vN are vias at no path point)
3V3: C103.1 C104.1 FB1.1 FB2.1 FB201.1 FB300.1 FB302.1 R100.1 R102.1 R202.2 U100.6 | length 2651.9
  Top Layer w24: FB302.1@2301.57,2828.5 2495.07,2828.5 2502.57,2836 ; FB300.1@2301.57,3033.5 2470.07,3033.5 2556.57,3120 FB1.1@2556.57,3263.5 ; FB300.1@2306.57,3032 2502.57,2836 ; U100.6@2665.68,2518.5 2666.08,2518.1 2695.47,2518.1 2745.07,2468.5 2855.52,2468.5 2882.02,2495 C104.1@2970.07,2495 ; R100.1@2781.57,2663.5 2781.57,2662 2823.57,2620 2885.07,2620 R102.1@2890.07,2625 2965.48,2625 ; FB2.1@2875.86,2998.5 C103.1@2875.86,2823.5 ; C104.1@2971.57,2495 C104.1@2970.07,2495 ; FB201.1@3033.57,2623.5 2973.16,2623.5 2970.07,2620.41 ; R202.2@3176.07,2538.5 3171.07,2543.5 2970.07,2543.5 ; 2502.57,2836 2515.07,2823.5 C103.1@2875.86,2823.5 ; C103.1@2875.86,2823.5 2970.07,2729.29 2970.07,2620.41 ; C104.1@2970.07,2495 2970.07,2543.5 ; 2970.07,2543.5 2970.07,2620.41
3V3_BTN: FB201.2 R208.2 R209.2 R210.2 R211.2 | length 3490.4
  Top Layer w9: FB201.2@3096.57,2623.5 3245.07,2772 v1(3245.07,2773.5) ; R209.2@3150.07,4161.4 3152.17,4163.5 3485.07,4163.5 3530.16,4118.41 ; R210.2@3150.07,4576.4 3492.17,4576.4 3530.16,4538.41 3530.16,4118.41 ; R208.2@3165.07,3767.71 3165.86,3768.5 3499.98,3768.5 3530.16,3738.33 ; R211.2@3175.07,3367 3176.57,3365.5 3176.57,3308.43 3219.5,3265.5 3322.06,3265.5 ; v1(3322.06,2850.5) 3322.06,3265.5 ; v1(3390.07,3373.5) 3390.07,3333.5 3322.06,3265.5 ; v1(3390.07,3453.5) 3530.16,3593.59 3530.16,3738.33 ; 3530.16,3738.33 3530.16,4118.41
  Bottom Layer w9: v1(3245.07,2773.5) v1(3322.06,2850.5) ; v1(3390.07,3373.5) v1(3390.07,3453.5)
3V3_CP: C300.1 C301.1 FB300.2 R300.2 R301.2 R302.1 R305.2 U301.6 U301.7 | length 1442.9
  Top Layer w8: R300.2@1946.57,3613.5 R300.2@1946.57,3618.5 ; R301.2@1946.57,3683.5 R300.2@1946.57,3618.5 ; R300.2@1946.7,3614.87 R300.2@1951.57,3614.87 ; R300.2@1948.07,3621.5 R300.2@1948.07,3620 ; R300.2@1951.57,3623.5 R300.2@1948.07,3620 ; R301.2@1951.57,3673.5 R300.2@1951.57,3614.87 ; R300.2@1961.07,3602.5 1951.57,3612 R300.2@1951.57,3614.87 ; v1@1989.7,3589.87 v1(1992.41,3589.87) ; U301.6@2044.28,3269.29 2044.8,3269.81 2044.8,3287.07 2046.71,3288.97 U301.7@2056.09,3288.97 2075.07,3288.97 ; R305.2@2117.07,3463.29 2117.07,3458 R305.2@2131.57,3443.5 ; C301.1@2130.07,3278 C301.1@2140.57,3288.5 ; C301.1@2130.07,3288.5 2129.6,3288.97 2075.07,3288.97 ; R305.2@2131.57,3438.5 2146.07,3424 2146.07,3415.5 2191.57,3370 R302.1@2191.57,3368.5 2280.07,3368.5 2330,3318.57 2330,3120 2278.3,3068.3 2238.57,3068.3 FB300.2@2238.57,3033.5 2195,3077.07 v1(2195,3080) ; C300.1@2135.07,3159 C300.1@2133.57,3159 ; v1(2155,3120) 2141.81,3133.19 2141.81,3150.75 C300.1@2133.57,3159 ; R300.2@1946.57,3618.5 R300.2@1948.07,3620 ; 2075.07,3288.97 2075.07,3217.5 C300.1@2133.57,3159
  Top Layer w9: R300.2@1961.07,3602.5 1977.07,3602.5 v1@1989.7,3589.87 ; v1(2054.91,3525.45) R305.2@2117.07,3463.29
  Bottom Layer w8: v1@1992.41,3588.91 v1(1992.41,3589.87) ; v1(2054.91,3525.45) v1@2054.91,3526.41 ; v1(2155,3120) v1(2195,3080)
  Bottom Layer w9: v1@1992.41,3588.91 v1@2054.91,3526.41
3V3_ESP: C202.1 C203.1 R200.1 R202.1 R203.2 R204.2 R205.1 U200.1 | length 4959.9
  Top Layer w15: R205.1@3345.07,1772 3338.07,1765 2880,1765 2780.07,1864.93 2780.07,2288.5 2875.07,2383.5 3200.07,2383.5 3230.07,2413.5 3230.07,2427.5 C202.1@3241.07,2438.5 3240.07,2439.5 3240.07,2537.5 R202.1@3239.07,2538.5 3239.07,2540 3356.99,2657.93 3359.49,2657.93 v1(3360.07,2658.5) ; v1(3448.63,2745.15) 3449.44,2745.15 3456.08,2738.5 3764.28,2738.5 R203.2@3770.07,2732.71 ; v1@3450.57,2747.01 3573.34,2869.79 3573.34,2897.23 3570.07,2900.5 3570.07,2973.5 ; R200.1@3650.07,2977.71 3651.57,2977.71 3655.78,2973.5 3570.07,2973.5 ; U200.1@4264.04,1775.39 4274.26,1785.61 4296.74,1785.61 4405,1893.87 4405,2107.21 4405.57,2107.78 4405.57,2117.5 R204.2@4416.57,2128.5 ; R204.2@4416.57,2130 4427.57,2141 4429.07,2141 4505,2216.93 4505,2823.57 4228.57,3100 3631.57,3100 3570.07,3038.5 3570.07,2973.5
  Bottom Layer w15: v1(3360.07,2658.5) 3409.49,2707.92 3411.4,2707.92 v1(3448.63,2745.15)
3V3_EXT: 1.3 3.1 5.1 FB2.2 R4.2 R5.2 | length 6171.7
  Top Layer w10: 1.3@2055.07,3873.5 1875.07,3873.5 1720.07,4028.5 1720.07,4543.5 1794.62,4618.06 1907.91,4618.06 2031.03,4494.93 2146.5,4494.93 2283.12,4631.56 2830.07,4631.56 ; R4.2@2663.5,4185 2663.5,4251.5 2677,4265 2678.5,4265 2734.98,4321.48 2734.98,4428.42 3.1@2830.07,4523.5 2830.07,4631.56 ; 2957.16,3399.9 3526.47,3399.9 3635.07,3508.5 3635.07,4733.5 3525.07,4843.5 3000.07,4843.5 2830.07,4673.5 2830.07,4631.56
  Top Layer w11: 5.1@2830.07,3518.5 2835.89,3518.5 2860.05,3494.34 2862.72,3494.34 2957.16,3399.9 2993.06,3364 v1(2993.06,3180.71) ; FB2.2@2874.36,3059.25 2913.61,3098.5 v1(2915.07,3098.5)
  Bottom Layer w11: v1(2915.07,3098.5) 2991.72,3175.15 2991.72,3179.37 v1(2993.06,3180.71)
